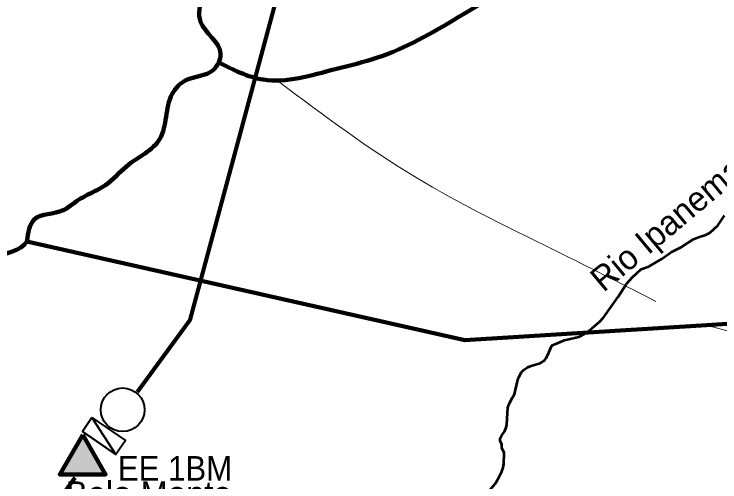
# Model space of a CAD drawing. Extents: x 553962 to 842807, y 8883888 to 9032388.
# Drawn here: x 688144 to 702536, y 8913971 to 8923504 of the extents above; entities that cross this region are included whole.
import ezdxf
from ezdxf.enums import TextEntityAlignment as Align

# ---------------------------------------------------------------- set-up
doc = ezdxf.new("R2010")
doc.units = 0
doc.header["$LTSCALE"] = 200
for name, color, linetype, lineweight in [('24', 7, 'Continuous', 25), ('28', 7, 'Continuous', 40), ('41', 7, 'Continuous', 40), ('57', 7, 'Continuous', 13), ('9', 7, 'Continuous', 90)]:
    doc.layers.add(name, color=color, linetype=linetype, lineweight=lineweight)
doc.layers.add('49', color=7, linetype='Continuous')

msp = doc.modelspace()

# ---------------------------------------------------------------- hatches: boundary and pattern name
at = {"layer": '28'}
msp.add_hatch(color=256, dxfattribs=at).paths.add_polyline_path([(689542.1, 8914929.3), (690008.2, 8914122), (689075.9, 8914122)])

# ---------------------------------------------------------------- linework, layer by layer
at = {"layer": '24', "lineweight": 53}
for points in [[(700933.1, 8918304.1), (701087.7, 8918357.1), (701353.2, 8918514.3), (701545, 8918649.8), (701747.7, 8918756.1), (702001.1, 8918916), (702097.1, 8918956.4), (702250.9, 8919005.3), (702331, 8919046.8), (702493.5, 8919198.3), (702630.7, 8919399.1)], [(699106, 8916749.2), (699107.9, 8916751.8), (699364.4, 8916858.8), (699663.1, 8916929.4), (699774, 8916985.7), (699929.5, 8917100.9), (700086.2, 8917240.2), (700161.8, 8917318.8), (700161.8, 8917318.8), (700462.7, 8917739.7), (700633.3, 8918009.2), (700747.4, 8918139), (700925.2, 8918301.4), (700933.1, 8918304.1)], [(698310.3, 8915692), (698345.2, 8915759.1), (698414.2, 8916049.1), (698434, 8916103.3), (698493.2, 8916205.4), (698541, 8916255.4), (698604.5, 8916300.2), (698689, 8916338.6), (698872.4, 8916392.4), (698958.8, 8916447.6), (698989, 8916484.6), (699031.1, 8916558.4), (699106, 8916749.2)], [(698089.5, 8914668.2), (698093, 8914730.9), (698057.9, 8914805.5), (698057.7, 8914860.2), (698080.5, 8914908.2), (698146.1, 8914998.1), (698179.3, 8915082.2), (698193.2, 8915143.2), (698213.4, 8915483.8), (698249.4, 8915574.9), (698249.4, 8915574.9), (698310.3, 8915692)], [(697317.1, 8913373.6), (697317.9, 8913374.9), (697500, 8913466.1), (697607.5, 8913547.4), (697828, 8913780.1), (697955.3, 8913931.9), (698021, 8914043.8), (698087.2, 8914183.8), (698114.2, 8914261.7), (698128.6, 8914336.6), (698136.1, 8914565.5), (698089.3, 8914664.5), (698089.5, 8914668.2)]]:
    msp.add_lwpolyline(points, dxfattribs=at)
at = {"layer": '24'}
for points in [[(700933.1, 8918304.1), (701087.7, 8918357.1), (701353.2, 8918514.3), (701545, 8918649.8), (701747.7, 8918756.1), (702001.1, 8918916), (702097.1, 8918956.4), (702250.9, 8919005.3), (702331, 8919046.8), (702493.5, 8919198.3), (702630.7, 8919399.1)], [(699106, 8916749.2), (699107.9, 8916751.8), (699364.4, 8916858.8), (699663.1, 8916929.4), (699774, 8916985.7), (699929.5, 8917100.9), (700086.2, 8917240.2), (700161.8, 8917318.8), (700161.8, 8917318.8), (700462.7, 8917739.7), (700633.3, 8918009.2), (700747.4, 8918139), (700925.2, 8918301.4), (700933.1, 8918304.1)], [(698310.3, 8915692), (698345.2, 8915759.1), (698414.2, 8916049.1), (698434, 8916103.3), (698493.2, 8916205.4), (698541, 8916255.4), (698604.5, 8916300.2), (698689, 8916338.6), (698872.4, 8916392.4), (698958.8, 8916447.6), (698989, 8916484.6), (699031.1, 8916558.4), (699106, 8916749.2)], [(698089.5, 8914668.2), (698093, 8914730.9), (698057.9, 8914805.5), (698057.7, 8914860.2), (698080.5, 8914908.2), (698146.1, 8914998.1), (698179.3, 8915082.2), (698193.2, 8915143.2), (698213.4, 8915483.8), (698249.4, 8915574.9), (698249.4, 8915574.9), (698310.3, 8915692)], [(697317.1, 8913373.6), (697317.9, 8913374.9), (697500, 8913466.1), (697607.5, 8913547.4), (697828, 8913780.1), (697955.3, 8913931.9), (698021, 8914043.8), (698087.2, 8914183.8), (698114.2, 8914261.7), (698128.6, 8914336.6), (698136.1, 8914565.5), (698089.3, 8914664.5), (698089.5, 8914668.2)]]:
    msp.add_lwpolyline(points, dxfattribs=at)
at = {"layer": '28', "lineweight": 80}
msp.add_line((688967.9, 8913483.7), (689387.7, 8914059), dxfattribs=at)
msp.add_lwpolyline([(690660.6, 8915803.9), (691732.9, 8917273.7), (693879.2, 8925258.2), (694473.3, 8927056.5)], dxfattribs=at)
at = {"layer": '28'}
msp.add_lwpolyline([(689728.8, 8915279.8), (690414, 8914811.8), (690221.2, 8914529.4), (689535.9, 8914997.5)], close=True, dxfattribs=at)
for points in [[(689728.8, 8915279.8), (689535.9, 8914997.5), (690221.2, 8914529.4)], [(689728.8, 8915279.8), (690221.2, 8914529.4), (689728.8, 8915279.8)]]:
    msp.add_lwpolyline(points, dxfattribs=at)
at = {"layer": '28', "lineweight": 90}
msp.add_lwpolyline([(689542.1, 8914929.3), (690008.2, 8914122), (689075.9, 8914122)], close=True, dxfattribs=at)
at = {"layer": '28'}
msp.add_circle((690357.7, 8915440.2), 444.4, dxfattribs=at)
at = {"layer": '57'}
for p, q in [((688404.9, 8918868.1), (697336.5, 8916857.2)), ((697336.5, 8916857.2), (702263.2, 8917164.2))]:
    msp.add_line(p, q, dxfattribs=at)
for points in [[(702263.2, 8917164.2), (697336.5, 8916857.2), (688404.9, 8918868.1)], [(710120.3, 8913369), (709646.4, 8914096), (708983, 8914759.8), (708256.3, 8915202.3), (707118.9, 8915708.1), (706297.5, 8916055.8), (702263.2, 8917164.2)]]:
    msp.add_lwpolyline(points, dxfattribs=at)
for points in [[(688404.9, 8918868.1), (688561.4, 8919324.4), (689144.7, 8919506), (689372.6, 8919659.6), (689727.1, 8919864.8), (690005.8, 8920018.8), (690435.7, 8920401.8), (691118.7, 8920963.9), (691368.2, 8921877.4), (691646.2, 8922158), (692203.9, 8922364.7), (692354.7, 8922695), (691945.1, 8923350.3), (691968, 8923856.9), (691992.7, 8923983.7), (691990.8, 8924363.6), (691810.4, 8924894), (691605.7, 8925196.3), (690588.8, 8925391.4), (690130.9, 8925539.9), (689951.8, 8925791.8), (690098.6, 8926932.4), (689816.9, 8927386.1), (689611.9, 8927764.4), (689634.6, 8928296.3), (689708.3, 8928803.3), (689427.8, 8929029.1), (689071.1, 8929254.4), (688973.1, 8929278.1)], [(692314.9, 8922520), (692203.9, 8922364.7), (691646.2, 8922158), (691368.2, 8921877.4), (691118.7, 8920963.9), (690435.7, 8920401.8), (690005.8, 8920018.8), (689727.1, 8919864.8), (689372.6, 8919659.6), (689144.7, 8919506), (688561.4, 8919324.4), (688404.9, 8918868.1)], [(693559.8, 8922111.3), (693220.9, 8922169.7), (692314.9, 8922520)], [(701229.8, 8917650.5), (699357, 8918596.8), (696307.5, 8920193.1), (693559.8, 8922111.3)], [(688404.9, 8918868.1), (688360.8, 8918816.4), (687575, 8918481.4), (687019.1, 8917894.9), (686664.7, 8917664.4)], [(686702.4, 8917687.5), (687019.1, 8917894.9), (687575, 8918481.4), (688360.8, 8918816.4), (688404.9, 8918868.1)]]:
    msp.add_spline(points, degree=3, dxfattribs=at)
at = {"layer": '9'}
msp.add_line((702263.2, 8917164.2), (717332.2, 8918103.3), dxfattribs=at)
msp.add_lwpolyline([(688404.9, 8918868.1), (697336.5, 8916857.2), (702263.2, 8917164.2)], dxfattribs=at)
for points in [[(702208.9, 8933124.7), (702148.3, 8929984.4), (701978.2, 8928413.1), (700513.8, 8926655.1), (699226.8, 8924948.9), (697202.3, 8923439.9), (695555.4, 8922617.4), (694693, 8922383.1), (693220.9, 8922169.7), (692314.9, 8922520)], [(688404.9, 8918868.1), (688561.4, 8919324.4), (689144.7, 8919506), (689372.6, 8919659.6), (689727.1, 8919864.8), (690005.8, 8920018.8), (690435.7, 8920401.8), (691118.7, 8920963.9), (691368.2, 8921877.4), (691646.2, 8922158), (692203.9, 8922364.7), (692354.7, 8922695), (691945.1, 8923350.3), (691968, 8923856.9), (691992.7, 8923983.7), (691990.8, 8924363.6), (691810.4, 8924894), (691605.7, 8925196.3), (690588.8, 8925391.4), (690130.9, 8925539.9), (689951.8, 8925791.8), (690098.6, 8926932.4), (689816.9, 8927386.1), (689611.9, 8927764.4), (689634.6, 8928296.3), (689708.3, 8928803.3), (689427.8, 8929029.1), (689071.1, 8929254.4), (688969.4, 8929279)], [(685563.3, 8914000.1), (685411.9, 8914186), (685156.8, 8914412), (685077.7, 8914993.8), (685249.9, 8916134.6), (685677.5, 8916973.4), (686082.1, 8917330.9), (686664.7, 8917664.4), (687019.1, 8917894.9), (687575, 8918481.4), (688360.8, 8918816.4), (688404.9, 8918868.1)]]:
    msp.add_spline(points, degree=3, dxfattribs=at)

# ---------------------------------------------------------------- texts
at = {"layer": '28', "width": 0.95}
msp.add_text('EE 1BM', height=500, dxfattribs=at).set_placement((690259.9, 8913996.5))
at = {"layer": '41'}
msp.add_text('Belo Monte', height=500, dxfattribs=at).set_placement((689197.5, 8913481.5))
at = {"layer": '49'}
msp.add_text('Rio Ipanema', height=500, rotation=39.92, dxfattribs=at).set_placement((701615.3, 8919036.7), align=Align.CENTER)

doc.saveas('drawing.dxf')
